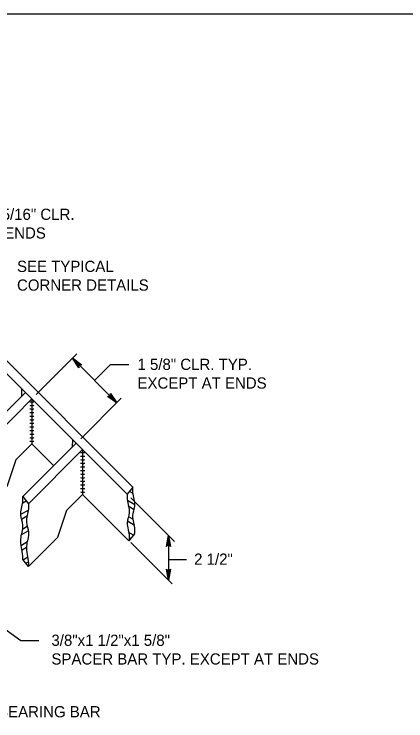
# Model space of a CAD drawing. Extents: x 2087776 to 2104538, y 970919 to 982612.
# Drawn here: x 2097646 to 2097990, y 979994 to 980614 of the extents above; entities that cross this region are included whole.
import ezdxf

# ---------------------------------------------------------------- set-up
doc = ezdxf.new("R2010")
doc.units = 0
doc.layers.add('1', color=7, linetype='Continuous')

msp = doc.modelspace()

# ---------------------------------------------------------------- linework, layer by layer
at = {"layer": '1'}
for p, q in [((2097750.57, 980199.1), (2097528.26, 980421.4)), ((2097745.6, 980192.92), (2097522.69, 980415.83)), ((2097665.79, 980280.53), (2097701.34, 980316.08)), ((2097697.44, 980312.18), (2097736.41, 980273.21)), ((2097716.92, 980292.7), (2097730.57, 980306.33)), ((2097609.47, 980235.35), (2097656.32, 980282.2)), ((2097614.43, 980229.17), (2097661.89, 980276.63)), ((2097661.89, 980276.63), (2097661.89, 980237.26)), ((2097704.76, 980241.56), (2097740.31, 980277.11)), ((2097647.75, 980223.12), (2097661.89, 980237.26)), ((2097654.01, 980190.8), (2097700.86, 980237.66)), ((2097658.97, 980184.63), (2097706.43, 980232.09)), ((2097681.18, 980217.97), (2097661.89, 980237.26)), ((2097706.43, 980232.09), (2097706.43, 980192.72)), ((2097706.43, 980232.09), (2097706.43, 980200.59)), ((2097647.75, 980223.12), (2097639.88, 980199.51)), ((2097750.57, 980199.1), (2097745.6, 980192.92)), ((2097750.57, 980199.1), (2097745.6, 980192.92)), ((2097654.01, 980190.8), (2097658.97, 980184.63)), ((2097692.29, 980178.57), (2097706.43, 980192.72)), ((2097747.03, 980152.12), (2097706.43, 980192.72)), ((2097748.89, 980189.63), (2097787.03, 980151.49)), ((2097692.29, 980178.57), (2097684.42, 980154.96)), ((2097751.99, 980158.29), (2097747.03, 980152.11)), ((2097658.97, 980129.51), (2097684.42, 980154.96)), ((2097781.78, 980156.74), (2097781.78, 980117.37)), ((2097748.6, 980150.55), (2097784.98, 980114.17)), ((2097658.97, 980129.51), (2097654.01, 980135.68)), ((2097797.71, 980135.42), (2097781.78, 980135.42)), ((2097652.37, 980064.28), (2097630.72, 980079.65)), ((2097668.11, 980064.28), (2097652.37, 980064.28))]:
    msp.add_line(p, q, dxfattribs=at)
for points in [[(2098759.93, 978763.82), (2098759.93, 980614.22), (2096181.19, 980614.22), (2096181.19, 978763.82), (2098759.93, 978763.82), (2098759.93, 978850.3), (2098103.76, 978850.3), (2098103.76, 979062.5), (2098759.93, 979062.5), (2098759.93, 979157.53), (2098103.76, 979157.53), (2098103.76, 978763.82), (2098362.29, 978763.82), (2098362.29, 978850.3), (2098362.29, 978763.82), (2098614.92, 978763.82), (2098614.92, 978850.3), (2098614.92, 978809.9), (2098759.93, 978809.9)], [(2097697.44, 980312.18), (2097705.66, 980306.56), (2097705.21, 980306.64), (2097704.76, 980306.72), (2097704.39, 980306.63), (2097704.02, 980306.53), (2097703.75, 980306.34), (2097703.47, 980306.15), (2097703.28, 980305.88), (2097703.09, 980305.6), (2097702.99, 980305.23), (2097702.9, 980304.87), (2097702.98, 980304.41), (2097703.06, 980303.96), (2097697.44, 980312.18), (2097702.98, 980304.41), (2097702.9, 980304.87), (2097697.44, 980312.18), (2097702.99, 980305.23), (2097703.09, 980305.6), (2097697.44, 980312.18), (2097703.28, 980305.88), (2097703.47, 980306.15), (2097697.44, 980312.18), (2097703.75, 980306.34), (2097704.02, 980306.53), (2097697.44, 980312.18), (2097704.39, 980306.63), (2097704.76, 980306.72), (2097697.44, 980312.18), (2097705.21, 980306.64)], [(2097747.1, 980306.33), (2097730.57, 980306.33)], [(2097736.41, 980273.21), (2097728.2, 980278.83), (2097728.65, 980278.75), (2097729.1, 980278.67), (2097729.47, 980278.76), (2097729.84, 980278.86), (2097730.11, 980279.05), (2097730.38, 980279.24), (2097730.57, 980279.51), (2097730.76, 980279.78), (2097730.86, 980280.15), (2097730.95, 980280.52), (2097730.87, 980280.98), (2097730.79, 980281.43), (2097736.41, 980273.21), (2097730.87, 980280.98), (2097730.95, 980280.52), (2097736.41, 980273.21), (2097730.86, 980280.15), (2097730.76, 980279.78), (2097736.41, 980273.21), (2097730.57, 980279.51), (2097730.38, 980279.24), (2097736.41, 980273.21), (2097730.11, 980279.05), (2097729.84, 980278.86), (2097736.41, 980273.21), (2097729.47, 980278.76), (2097729.1, 980278.67), (2097736.41, 980273.21), (2097728.65, 980278.75)], [(2097750.69, 980193.59), (2097747.59, 980195.39)], [(2097750.57, 980198.21), (2097750.08, 980198.49)], [(2097654, 980189.92), (2097654.5, 980190.2)], [(2097653.88, 980185.3), (2097656.99, 980187.09)], [(2097752.24, 980183.6), (2097745.74, 980187.36)], [(2097652.33, 980175.32), (2097658.84, 980179.07)], [(2097751.79, 980179.32), (2097746.43, 980182.42)], [(2097652.78, 980171.03), (2097658.15, 980174.13)], [(2097750.99, 980170.69), (2097746.79, 980173.12)], [(2097653.58, 980162.4), (2097657.78, 980164.83)], [(2097752.05, 980165.53), (2097745.78, 980169.15)], [(2097652.53, 980157.24), (2097658.8, 980160.87)], [(2097751, 980157.05), (2097747.1, 980159.3)], [(2097748.5, 980153.94), (2097747.26, 980154.65)], [(2097781.78, 980156.74), (2097783.61, 980146.95), (2097783.35, 980147.33), (2097783.09, 980147.71), (2097782.76, 980147.9), (2097782.44, 980148.1), (2097782.11, 980148.15), (2097781.78, 980148.21), (2097781.45, 980148.15), (2097781.12, 980148.1), (2097780.8, 980147.9), (2097780.47, 980147.71), (2097780.21, 980147.33), (2097779.94, 980146.95), (2097781.78, 980156.74), (2097780.21, 980147.33), (2097780.47, 980147.71), (2097781.78, 980156.74), (2097780.8, 980147.9), (2097781.12, 980148.1), (2097781.78, 980156.74), (2097781.45, 980148.15), (2097781.78, 980148.21), (2097781.78, 980156.74), (2097782.11, 980148.15), (2097782.44, 980148.1), (2097781.78, 980156.74), (2097782.76, 980147.9), (2097783.09, 980147.71), (2097781.78, 980156.74), (2097783.35, 980147.33)], [(2097652.89, 980148.37), (2097657.47, 980151.01)], [(2097653.41, 980144.12), (2097657.3, 980146.37)], [(2097654.19, 980135.47), (2097658.37, 980137.89)], [(2097656.68, 980132.36), (2097658.83, 980133.61)], [(2097781.78, 980117.37), (2097779.94, 980127.15), (2097780.21, 980126.78), (2097780.47, 980126.4), (2097780.8, 980126.2), (2097781.12, 980126.01), (2097781.45, 980125.95), (2097781.78, 980125.9), (2097782.11, 980125.95), (2097782.44, 980126.01), (2097782.76, 980126.2), (2097783.09, 980126.4), (2097783.35, 980126.78), (2097783.61, 980127.15), (2097781.78, 980117.37), (2097783.35, 980126.78), (2097783.09, 980126.4), (2097781.78, 980117.37), (2097782.76, 980126.2), (2097782.44, 980126.01), (2097781.78, 980117.37), (2097782.11, 980125.95), (2097781.78, 980125.9), (2097781.78, 980117.37), (2097781.45, 980125.95), (2097781.12, 980126.01), (2097781.78, 980117.37), (2097780.8, 980126.2), (2097780.47, 980126.4), (2097781.78, 980117.37), (2097780.21, 980126.78)]]:
    msp.add_lwpolyline(points, dxfattribs=at)
for points in [[(2097652.94, 980285.58), (2097652.83, 980278.73), (2097656.32, 980282.2)], [(2097697.48, 980241.04), (2097697.37, 980234.18), (2097700.86, 980237.66)]]:
    msp.add_lwpolyline(points, close=True, dxfattribs=at)
for points in [[(2097660.12, 980274.12), (2097661.58, 980273.98), (2097662.9, 980273.98), (2097663.78, 980274.12)], [(2097660.12, 980270.97), (2097661.58, 980270.83), (2097662.9, 980270.83), (2097663.78, 980270.97)], [(2097660.12, 980267.82), (2097661.58, 980267.68), (2097662.9, 980267.68), (2097663.78, 980267.82)], [(2097660.12, 980264.67), (2097661.58, 980264.53), (2097662.9, 980264.53), (2097663.78, 980264.67)], [(2097660.12, 980261.52), (2097661.58, 980261.38), (2097662.9, 980261.38), (2097663.78, 980261.52)], [(2097660.12, 980258.37), (2097661.58, 980258.23), (2097662.9, 980258.23), (2097663.78, 980258.37)], [(2097660.12, 980255.22), (2097661.58, 980255.08), (2097662.9, 980255.08), (2097663.78, 980255.22)], [(2097660.12, 980252.07), (2097661.58, 980251.93), (2097662.9, 980251.93), (2097663.78, 980252.07)], [(2097660.12, 980248.92), (2097661.58, 980248.78), (2097662.9, 980248.78), (2097663.78, 980248.92)], [(2097660.12, 980245.78), (2097661.58, 980245.63), (2097662.9, 980245.63), (2097663.78, 980245.78)], [(2097660.12, 980242.63), (2097661.58, 980242.48), (2097662.9, 980242.48), (2097663.78, 980242.63)], [(2097660.12, 980239.48), (2097661.58, 980239.33), (2097662.9, 980239.33), (2097663.78, 980239.48)], [(2097704.67, 980229.58), (2097706.13, 980229.43), (2097707.44, 980229.43), (2097708.32, 980229.58)], [(2097704.67, 980226.43), (2097706.13, 980226.28), (2097707.44, 980226.28), (2097708.32, 980226.43)], [(2097704.67, 980223.28), (2097706.13, 980223.13), (2097707.44, 980223.13), (2097708.32, 980223.28)], [(2097704.67, 980220.13), (2097706.13, 980219.98), (2097707.44, 980219.98), (2097708.32, 980220.13)], [(2097704.67, 980216.98), (2097706.13, 980216.83), (2097707.44, 980216.83), (2097708.32, 980216.98)], [(2097704.67, 980213.83), (2097706.13, 980213.68), (2097707.44, 980213.68), (2097708.32, 980213.83)], [(2097704.67, 980210.68), (2097706.13, 980210.53), (2097707.44, 980210.53), (2097708.32, 980210.68)], [(2097704.67, 980207.53), (2097706.13, 980207.38), (2097707.44, 980207.38), (2097708.32, 980207.53)], [(2097704.67, 980204.38), (2097706.13, 980204.23), (2097707.44, 980204.23), (2097708.32, 980204.38)], [(2097704.67, 980201.23), (2097706.13, 980201.08), (2097707.44, 980201.08), (2097708.32, 980201.23)], [(2097704.67, 980198.08), (2097706.13, 980197.93), (2097707.44, 980197.93), (2097708.32, 980198.08)], [(2097704.67, 980194.94), (2097706.13, 980194.78), (2097707.44, 980194.78), (2097708.32, 980194.94)], [(2097751.99, 980158.29), (2097752.36, 980161.83), (2097750.6, 980174.11), (2097752.36, 980182.88), (2097750.6, 980194.57), (2097750.57, 980199.1)], [(2097654.01, 980135.68), (2097653.97, 980138.92), (2097652.22, 980153.54), (2097653.97, 980165.81), (2097652.22, 980174.59), (2097653.97, 980186.29), (2097654.01, 980190.8)], [(2097745.6, 980192.92), (2097745.64, 980188.4), (2097747.4, 980176.7), (2097745.64, 980167.93), (2097747.4, 980155.65), (2097747.03, 980152.11)], [(2097658.97, 980184.63), (2097658.93, 980180.11), (2097657.18, 980168.41), (2097658.93, 980159.64), (2097657.18, 980147.36), (2097658.93, 980132.74), (2097658.97, 980129.51)]]:
    msp.add_spline(points, degree=3, dxfattribs=at)

# ---------------------------------------------------------------- texts
for s, height, p in [('1 15/16" CLR.', 9.8425, (2097617.12, 980433.65)), ('AT ENDS', 9.843, (2097617.12, 980417.25)), ('SEE TYPICAL', 9.8425, (2097648.87, 980387.96)), ('CORNER DETAILS', 9.8425, (2097648.87, 980371.56)), ('1 5/8" CLR. TYP.', 9.8425, (2097754.56, 980302)), ('EXCEPT AT ENDS', 9.8425, (2097754.56, 980285.59)), ('2 1/2"', 9.843, (2097804.28, 980131.05)), ('3/8"x1 1/2"x1 5/8" ', 9.8425, (2097679.07, 980059.86)), ('SPACER BAR TYP. EXCEPT AT ENDS', 9.8425, (2097679.07, 980043.45)), ('BEARING BAR', 9.8425, (2097632.29, 979997.15))]:
    msp.add_text(s, height=height, dxfattribs=at).set_placement(p)

doc.saveas('drawing.dxf')
